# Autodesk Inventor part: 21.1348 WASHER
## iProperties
Created: 2011-09
Part Number: 21.1348 WASHER
Material: Alloy Steel
Document SubType Name: Modeling
Designer: Administrator
Mass: 1.72898 g
Surface Area: 4.14986 cm^2
Volume: 0.220252 cm^3
Density: 7.85 g/cm^3
Author: Administrator
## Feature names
1. Extrusion1
2. Extrusion2
3. Chamfer1
